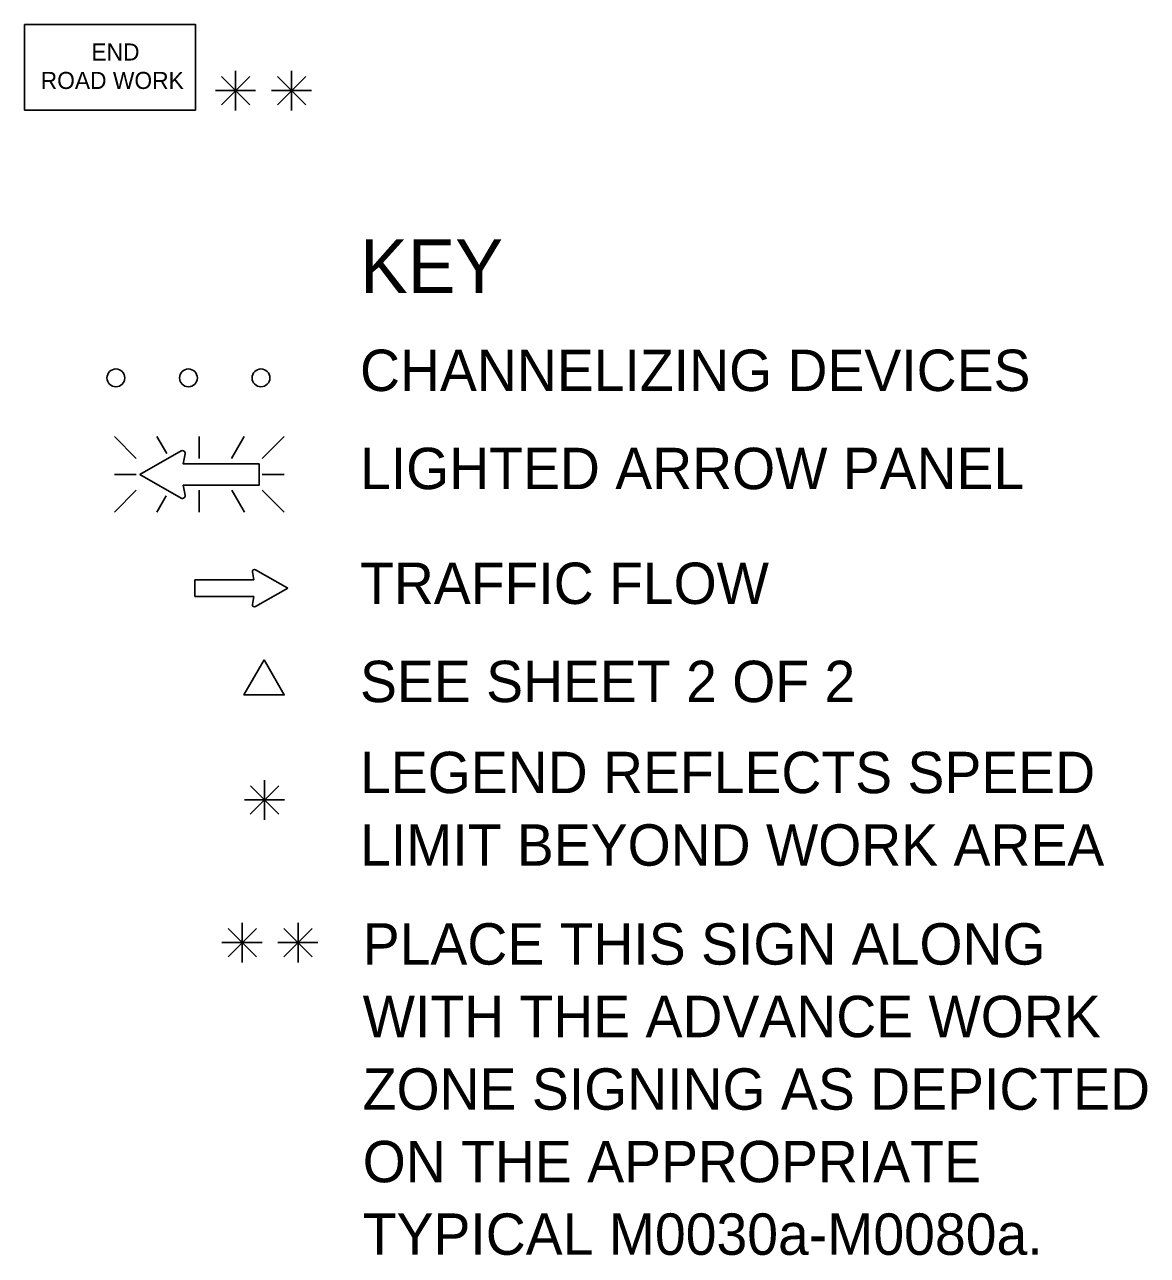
# Model space of a CAD drawing. Extents: x 16284 to 18468, y 5417 to 6974.
# Drawn here: x 17165.2 to 17417.5, y 6528.3 to 6804.8 of the extents above; entities that cross this region are included whole.
import ezdxf

# ---------------------------------------------------------------- set-up
doc = ezdxf.new("R2010")
doc.units = 0
for name, color, linetype in [('MT_SCRATCH_LEVEL_E', 7, 'Continuous'), ('TRAFFIC_SIGNS_PR', 7, 'Continuous'), ('TYPICAL_TEXT_DIMEN_EX', 7, 'Continuous'), ('TYPICAL_TEXT_DIMEN_PR', 7, 'Continuous')]:
    doc.layers.add(name, color=color, linetype=linetype)

msp = doc.modelspace()

# ---------------------------------------------------------------- linework, layer by layer
at = {"layer": 'MT_SCRATCH_LEVEL_E'}
for p, q in [((17216.36, 6681.88), (17216.68, 6680.1)), ((17224.29, 6678.25), (17217.04, 6682.36)), ((17216.68, 6680.1), (17203.42, 6680.1)), ((17203.42, 6680.1), (17203.42, 6676.36)), ((17203.42, 6676.36), (17216.68, 6676.36)), ((17216.68, 6676.36), (17216.36, 6674.58)), ((17217.04, 6674.1), (17224.29, 6678.25))]:
    msp.add_line(p, q, dxfattribs=at)
for centre, start, end in [((17216.82, 6681.95), 60.4248, 189.9638), ((17216.82, 6674.51), 170.0362, 299.7731)]:
    msp.add_arc(centre, 0.463, start, end, dxfattribs=at)
at = {"layer": 'TRAFFIC_SIGNS_PR'}
for p, q in [((17185.35, 6712.26), (17190.28, 6707.33)), ((17197.11, 6708.44), (17194.91, 6712.26)), ((17204.43, 6707.33), (17204.43, 6712.26)), ((17211.67, 6707.33), (17214.52, 6712.26)), ((17218.58, 6707.33), (17223.52, 6712.26)), ((17190.28, 6703.77), (17185.35, 6703.77)), ((17218.58, 6703.77), (17223.52, 6703.77)), ((17185.35, 6695.28), (17190.28, 6700.21)), ((17194.86, 6695.28), (17196.98, 6698.94)), ((17204.43, 6700.21), (17204.43, 6695.28)), ((17214.56, 6695.28), (17211.71, 6700.21)), ((17218.58, 6700.21), (17223.52, 6695.28))]:
    msp.add_line(p, q, dxfattribs=at)
msp.add_lwpolyline([(17165.18, 6785.64), (17203.58, 6785.64), (17203.58, 6804.84), (17165.18, 6804.84)], close=True, dxfattribs=at)
for points in [[(17200.36, 6709.05), (17191.07, 6703.77), (17200.36, 6698.45)], [(17201.24, 6699.08), (17200.84, 6701.35), (17217.85, 6701.35), (17217.85, 6706.15), (17200.84, 6706.15), (17201.24, 6708.43)]]:
    msp.add_lwpolyline(points, dxfattribs=at)
for centre in [(17185.69, 6725.46), (17201.99, 6725.46), (17218.29, 6725.46)]:
    msp.add_circle(centre, 2, dxfattribs=at)
for centre, radius, start, end in [((17200.65, 6708.52), 0.598, 350.7308, 118.8916), ((17200.65, 6698.97), 0.597, 241.4833, 9.9593)]:
    msp.add_arc(centre, radius, start, end, dxfattribs=at)
at = {"layer": 'TYPICAL_TEXT_DIMEN_PR'}
for p, q in [((17212.6, 6790.01), (17212.6, 6794.47)), ((17225.16, 6790.01), (17225.16, 6794.47)), ((17215.79, 6793.2), (17209.41, 6786.82)), ((17209.42, 6793.2), (17215.79, 6786.82)), ((17221.97, 6793.2), (17228.35, 6786.82)), ((17228.35, 6793.2), (17221.97, 6786.82)), ((17212.6, 6790.01), (17208.07, 6790.01)), ((17212.6, 6790.01), (17215.79, 6790.01)), ((17212.6, 6790.01), (17217.08, 6790.01)), ((17212.6, 6790.01), (17212.6, 6785.51)), ((17225.16, 6790.01), (17220.63, 6790.01)), ((17225.16, 6790.01), (17228.35, 6790.01)), ((17225.16, 6790.01), (17229.64, 6790.01)), ((17225.16, 6790.01), (17225.16, 6785.51)), ((17219.08, 6630.63), (17219.08, 6635.09)), ((17222.27, 6633.82), (17215.89, 6627.44)), ((17215.9, 6633.82), (17222.27, 6627.44)), ((17219.08, 6630.63), (17214.55, 6630.63)), ((17219.08, 6630.63), (17222.27, 6630.63)), ((17219.08, 6630.63), (17223.56, 6630.63)), ((17219.08, 6630.63), (17219.08, 6626.13)), ((17210.88, 6601.78), (17217.25, 6595.41)), ((17217.25, 6601.78), (17210.88, 6595.41)), ((17214.06, 6598.6), (17214.06, 6603.05)), ((17223.43, 6601.78), (17229.81, 6595.41)), ((17229.81, 6601.78), (17223.43, 6595.41)), ((17226.62, 6598.6), (17226.62, 6603.05)), ((17214.06, 6598.6), (17209.53, 6598.6)), ((17214.06, 6598.6), (17217.25, 6598.6)), ((17214.06, 6598.6), (17218.54, 6598.6)), ((17214.06, 6598.6), (17214.06, 6594.1)), ((17226.62, 6598.6), (17222.09, 6598.6)), ((17226.62, 6598.6), (17229.81, 6598.6)), ((17226.62, 6598.6), (17231.1, 6598.6)), ((17226.62, 6598.6), (17226.62, 6594.1))]:
    msp.add_line(p, q, dxfattribs=at)
msp.add_lwpolyline([(17219, 6662.08), (17214.47, 6654.24), (17223.52, 6654.24)], close=True, dxfattribs=at)

# ---------------------------------------------------------------- texts
at = {"layer": 'TRAFFIC_SIGNS_PR'}
for s, p in [('END', (17180.18, 6796.77)), ('ROAD WORK', (17168.79, 6790.38))]:
    msp.add_text(s, height=3.831, dxfattribs=at).set_placement(p)
at = {"layer": 'TYPICAL_TEXT_DIMEN_EX'}
for s, height, p in [('KEY', 12, (17240.54, 6744.56)), ('CHANNELIZING DEVICES', 9.3, (17240.54, 6722.51)), ('LIGHTED ARROW PANEL', 9.3, (17240.54, 6700.46)), ('TRAFFIC FLOW', 9.3, (17240.54, 6674.66)), ('SEE SHEET 2 OF 2', 9.3, (17240.54, 6652.61)), ('LEGEND REFLECTS SPEED', 9.3, (17240.54, 6632.16)), ('LIMIT BEYOND WORK AREA', 9.3, (17240.54, 6615.86)), ('PLACE THIS SIGN ALONG', 9.3, (17241.15, 6593.63)), ('WITH THE ADVANCE WORK', 9.3, (17241.15, 6577.33)), ('ZONE SIGNING AS DEPICTED', 9.3, (17241.15, 6561.03)), ('ON THE APPROPRIATE', 9.3, (17241.15, 6544.73)), ('TYPICAL M0030a-M0080a.', 9.3, (17241.15, 6528.43))]:
    msp.add_text(s, height=height, dxfattribs=at).set_placement(p)

doc.saveas('drawing.dxf')
